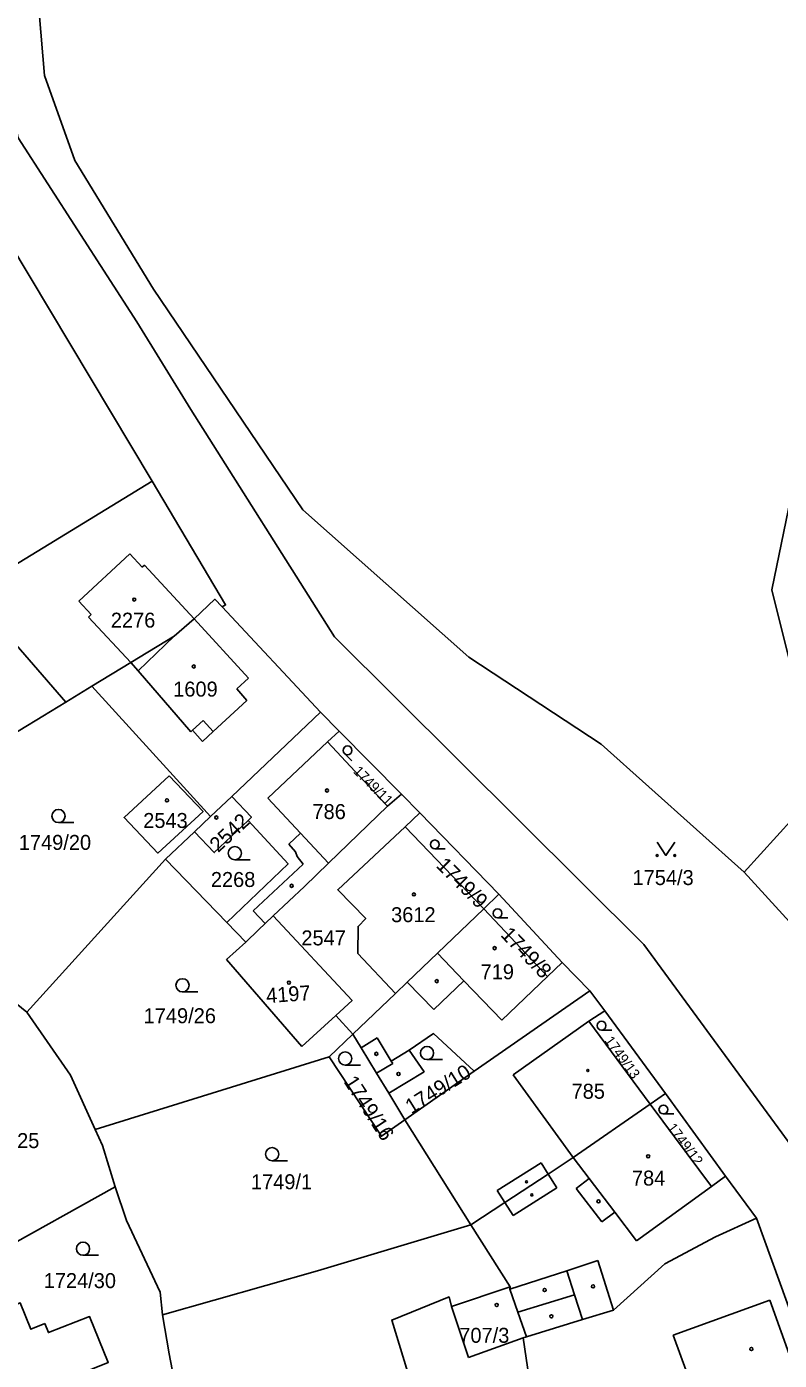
# Model space of a CAD drawing. Extents: x -679220 to -673243, y -1075091 to -1066557.
# Drawn here: x -676635.3 to -676549.8, y -1072087.4 to -1071935.7 of the extents above; entities that cross this region are included whole.
import ezdxf

# ---------------------------------------------------------------- set-up
doc = ezdxf.new("R2010")
doc.units = 0
for name, color, linetype in [('Hranice parcel', 7, 'Continuous'), ('Parcelní čísla', 7, 'Continuous'), ('Vnitřní kresba', 7, 'Continuous'), ('Značky budov', 7, 'Continuous'), ('Značky kultur', 7, 'Continuous')]:
    doc.layers.add(name, color=color, linetype=linetype)

msp = doc.modelspace()

# ---------------------------------------------------------------- linework, layer by layer
at = {"layer": 'Hranice parcel'}
for p, q in [((-676621.07, -1071987.4), (-676641.72, -1072000.02)), ((-676641.72, -1072000.02), (-676630.86, -1072012.51)), ((-676613.1, -1072001.69), (-676601.93, -1072013.64)), ((-676630.86, -1072012.51), (-676627.91, -1072010.71)), ((-676627.91, -1072010.71), (-676614.43, -1072025.51)), ((-676653.53, -1072026.32), (-676630.86, -1072012.51)), ((-676601.93, -1072013.64), (-676612.02, -1072023.23)), ((-676601.93, -1072013.64), (-676599.8, -1072015.8)), ((-676599.8, -1072015.8), (-676592.72, -1072022.97)), ((-676541.89, -1072018.69), (-676553.76, -1072031.84)), ((-676614.43, -1072025.51), (-676612.02, -1072023.23)), ((-676594.3, -1072024.34), (-676592.72, -1072022.97)), ((-676592.72, -1072022.97), (-676590.64, -1072025.11)), ((-676614.43, -1072025.51), (-676616.25, -1072027.25)), ((-676590.64, -1072025.11), (-676592.32, -1072026.68)), ((-676590.64, -1072025.11), (-676581.66, -1072034.34)), ((-676619.53, -1072030.36), (-676616.25, -1072027.25)), ((-676592.32, -1072026.68), (-676583.38, -1072036)), ((-676635.3, -1072047.75), (-676619.53, -1072030.36)), ((-676619.53, -1072030.36), (-676612.59, -1072037.56)), ((-676581.66, -1072034.34), (-676583.38, -1072036)), ((-676581.66, -1072034.34), (-676574.45, -1072042.12)), ((-676612.59, -1072037.56), (-676610.42, -1072039.82)), ((-676612.6, -1072041.77), (-676610.42, -1072039.82)), ((-676604.04, -1072051.67), (-676612.6, -1072041.77)), ((-676574.45, -1072042.12), (-676571.33, -1072045.34)), ((-676593.41, -1072045.63), (-676598.25, -1072050.28)), ((-676584.45, -1072054.47), (-676571.33, -1072045.34)), ((-676571.33, -1072045.34), (-676569.62, -1072047.62)), ((-676569.62, -1072047.62), (-676562.71, -1072057.02)), ((-676600.19, -1072048.13), (-676604.04, -1072051.67)), ((-676598.25, -1072050.28), (-676600.19, -1072048.13)), ((-676598.25, -1072050.28), (-676600.93, -1072052.86)), ((-676600.93, -1072052.86), (-676627.53, -1072061.09)), ((-676584.45, -1072054.47), (-676592.33, -1072060)), ((-676594.16, -1072056.99), (-676592.33, -1072060)), ((-676562.71, -1072057.02), (-676564.44, -1072058.21)), ((-676562.71, -1072057.02), (-676555.88, -1072066.4)), ((-676592.33, -1072060), (-676584.82, -1072071.93)), ((-676555.88, -1072066.4), (-676552.37, -1072071.2)), ((-676652.26, -1072082.65), (-676625.25, -1072067.62)), ((-676552.37, -1072071.2), (-676542.21, -1072099.31)), ((-676584.82, -1072071.93), (-676580.38, -1072079))]:
    msp.add_line(p, q, dxfattribs=at)
for points in [[(-676651.25, -1071520.53), (-676649.67, -1071525.28), (-676636.33, -1071567.59), (-676632.67, -1071580.29), (-676618.91, -1071616.92), (-676601.45, -1071672.26), (-676590.27, -1071707.98), (-676587.53, -1071724.18), (-676588.53, -1071766.09), (-676588.57, -1071776.49), (-676583.64, -1071788.99), (-676568.69, -1071809.98), (-676555.21, -1071828.53), (-676552.27, -1071835.54), (-676544.88, -1071865.16), (-676535.44, -1071910.25), (-676533.59, -1071921.04), (-676532.8, -1071927.61), (-676534.01, -1071935.8), (-676540.25, -1071959.64), (-676548.46, -1071989.23), (-676550.64, -1071999.75), (-676548.02, -1072010.25), (-676541.89, -1072018.69)], [(-676536.59, -1072122.5), (-676533.92, -1072098.22), (-676545.12, -1072067.43), (-676565.16, -1072040.09), (-676600.33, -1072005.09), (-676616.66, -1071979.22), (-676622.81, -1071969.28), (-676636.28, -1071948.34), (-676643.38, -1071915.55), (-676643.27, -1071912.66), (-676641.57, -1071878.93), (-676640.51, -1071869.39), (-676644.08, -1071858.21), (-676648.12, -1071848.64), (-676652.14, -1071843.11), (-676662.12, -1071830.1), (-676667.77, -1071822.29), (-676671.63, -1071816.16), (-676675.84, -1071808.46), (-676684.53, -1071784.41), (-676687.42, -1071776.51), (-676692.78, -1071762.77), (-676693.21, -1071759.8)], [(-676693.21, -1071759.8), (-676682.45, -1071780.64), (-676664.29, -1071814.93), (-676647.47, -1071846.25), (-676640.24, -1071862.09), (-676636.02, -1071877.65), (-676635.05, -1071901.27), (-676635.17, -1071919.29), (-676633.29, -1071941.26), (-676629.86, -1071950.91), (-676620.91, -1071965.54), (-676603.92, -1071990.64), (-676585.08, -1072007.38), (-676570.01, -1072017.31), (-676553.76, -1072031.84)], [(-676645.42, -1071936.13), (-676642.71, -1071947.04), (-676640.27, -1071954.61), (-676639.72, -1071956.26), (-676621.07, -1071987.4)], [(-676621.07, -1071987.4), (-676612.71, -1072001.45), (-676613.1, -1072001.69)], [(-676613.1, -1072001.69), (-676613.92, -1072000.81), (-676616.28, -1072003.03), (-676618.57, -1072005.02), (-676623.47, -1072008.01), (-676627.91, -1072010.71)], [(-676594.3, -1072024.34), (-676601.12, -1072017.04), (-676599.8, -1072015.8)], [(-676619.12, -1072020.89), (-676624.25, -1072025.62), (-676620.4, -1072029.67), (-676615.28, -1072024.94), (-676619.12, -1072020.89)], [(-676612.02, -1072023.23), (-676609.77, -1072025.59), (-676610.16, -1072025.96)], [(-676607.29, -1072036.83), (-676603.74, -1072033.46), (-676601, -1072030.84), (-676594.3, -1072024.34)], [(-676616.25, -1072027.25), (-676614.01, -1072029.61), (-676610.16, -1072025.96)], [(-676610.16, -1072025.96), (-676605.61, -1072030.88), (-676612.59, -1072037.56)], [(-676593.41, -1072045.63), (-676597.68, -1072041.1), (-676597.66, -1072038.02), (-676596.78, -1072037.12), (-676599.97, -1072033.85), (-676592.32, -1072026.68)], [(-676553.76, -1072031.84), (-676533.17, -1072054.44), (-676527.24, -1072064.82), (-676522.81, -1072075.75), (-676520.39, -1072086.47), (-676519.96, -1072097.33), (-676521.47, -1072117.29)], [(-676610.42, -1072039.82), (-676608.96, -1072038.42), (-676608.2, -1072037.7), (-676607.29, -1072036.83)], [(-676607.29, -1072036.83), (-676598.34, -1072046.42), (-676600.19, -1072048.13)], [(-676583.38, -1072036), (-676588.63, -1072041.05), (-676592.06, -1072044.34), (-676593.41, -1072045.63)], [(-676574.45, -1072042.12), (-676576.12, -1072043.71), (-676583.38, -1072036)], [(-676635.3, -1072047.75), (-676636.51, -1072046.77), (-676639.08, -1072044.43)], [(-676564.44, -1072058.21), (-676571.43, -1072048.77), (-676569.62, -1072047.62)], [(-676627.53, -1072061.09), (-676630.33, -1072054.92), (-676635.3, -1072047.75)], [(-676598.25, -1072050.28), (-676597.32, -1072051.81), (-676595.55, -1072054.71), (-676594.16, -1072056.99)], [(-676594.16, -1072056.99), (-676590.16, -1072054.55), (-676591.83, -1072052.1), (-676589.07, -1072050.2), (-676584.45, -1072054.47)], [(-676592.33, -1072060), (-676595, -1072061.87), (-676600.93, -1072052.86)], [(-676564.44, -1072058.21), (-676573.21, -1072064.31), (-676576.05, -1072066.17), (-676580.97, -1072069.4), (-676584.82, -1072071.93)], [(-676555.88, -1072066.4), (-676557.49, -1072067.59), (-676564.44, -1072058.21)], [(-676625.25, -1072067.62), (-676626.69, -1072062.94), (-676627.53, -1072061.09)], [(-676619.88, -1072082.19), (-676620.15, -1072079.6), (-676623.98, -1072071.44), (-676625.25, -1072067.62)], [(-676552.37, -1072071.2), (-676557.02, -1072073.3), (-676562.79, -1072076.4), (-676568.62, -1072081.66), (-676572.15, -1072082.73), (-676573.06, -1072079.9), (-676579.5, -1072081.87)], [(-676619.88, -1072082.19), (-676602.27, -1072077.16), (-676584.82, -1072071.93)], [(-676594.51, -1072100.12), (-676595.19, -1072097.87), (-676596.79, -1072093.24), (-676591.16, -1072091.48), (-676593.83, -1072082.77), (-676587.32, -1072080.15), (-676587.05, -1072081.24), (-676580.38, -1072079)], [(-676580.38, -1072079), (-676580.41, -1072079.26), (-676579.5, -1072081.87)], [(-676633.27, -1072083.18), (-676634.85, -1072083.83), (-676636.08, -1072080.81), (-676645.34, -1072084.58), (-676641.57, -1072093.86), (-676626.06, -1072087.6), (-676628.17, -1072082.38), (-676632.86, -1072084.2), (-676633.27, -1072083.18)], [(-676617.93, -1072092.96), (-676619.14, -1072086.6), (-676619.88, -1072082.19)], [(-676579.5, -1072081.87), (-676578.52, -1072084.67), (-676578.9, -1072084.79), (-676577.03, -1072097.37), (-676577.24, -1072097.44), (-676576.6, -1072102.13), (-676574.01, -1072101.78)]]:
    msp.add_lwpolyline(points, dxfattribs=at)
at = {"layer": 'Vnitřní kresba'}
for p, q in [((-676629.4, -1072001.02), (-676623.61, -1071995.66)), ((-676623.61, -1071995.66), (-676622.21, -1071997.18)), ((-676622.21, -1071997.18), (-676621.93, -1071996.93)), ((-676621.93, -1071996.93), (-676616.28, -1072003.03)), ((-676627.98, -1072002.56), (-676629.4, -1072001.02)), ((-676628.3, -1072002.85), (-676627.98, -1072002.56)), ((-676623.47, -1072008.01), (-676628.3, -1072002.85)), ((-676610.11, -1072009.79), (-676616.28, -1072003.03)), ((-676622.65, -1072008.95), (-676618.57, -1072005.02)), ((-676623.47, -1072008.01), (-676622.65, -1072008.95)), ((-676622.65, -1072008.95), (-676616.67, -1072015.87)), ((-676611.44, -1072011.01), (-676610.11, -1072009.79)), ((-676610.29, -1072012.33), (-676611.44, -1072011.01)), ((-676614.11, -1072015.84), (-676610.29, -1072012.33)), ((-676616.67, -1072015.87), (-676616.46, -1072015.69)), ((-676615.26, -1072014.59), (-676616.46, -1072015.69)), ((-676616.46, -1072015.69), (-676615.35, -1072016.97)), ((-676614.11, -1072015.84), (-676615.26, -1072014.59)), ((-676615.35, -1072016.97), (-676614.11, -1072015.84)), ((-676601.12, -1072017.04), (-676607.93, -1072023.42)), ((-676607.93, -1072023.42), (-676604.19, -1072027.41)), ((-676604.19, -1072027.41), (-676605.54, -1072028.68)), ((-676604.19, -1072027.41), (-676601, -1072030.84)), ((-676605.54, -1072028.68), (-676604.75, -1072029.52)), ((-676603.91, -1072030.92), (-676609.58, -1072036.23)), ((-676604.75, -1072029.52), (-676604.59, -1072030.05)), ((-676604.59, -1072030.05), (-676603.91, -1072030.92)), ((-676609.58, -1072036.23), (-676608.2, -1072037.7)), ((-676585.62, -1072044.19), (-676588.63, -1072041.05)), ((-676592.06, -1072044.34), (-676589.05, -1072047.48)), ((-676589.05, -1072047.48), (-676585.62, -1072044.19)), ((-676585.62, -1072044.19), (-676581.33, -1072048.67)), ((-676581.33, -1072048.67), (-676576.12, -1072043.71)), ((-676580.02, -1072054.91), (-676571.43, -1072048.77)), ((-676595.48, -1072050.7), (-676597.32, -1072051.81)), ((-676593.88, -1072053.34), (-676595.48, -1072050.7)), ((-676593.88, -1072053.34), (-676591.83, -1072052.1)), ((-676595.55, -1072054.71), (-676593.72, -1072053.6)), ((-676593.72, -1072053.6), (-676593.88, -1072053.34)), ((-676573.21, -1072064.31), (-676580.02, -1072054.91)), ((-676571.4, -1072066.69), (-676573.21, -1072064.31)), ((-676581.83, -1072068.04), (-676576.84, -1072064.91)), ((-676576.84, -1072064.91), (-676576.05, -1072066.17)), ((-676576.05, -1072066.17), (-676575.06, -1072067.75)), ((-676571.4, -1072066.69), (-676572.87, -1072067.81)), ((-676568.49, -1072070.5), (-676571.4, -1072066.69)), ((-676580.97, -1072069.4), (-676581.83, -1072068.04)), ((-676575.06, -1072067.75), (-676580.04, -1072070.88)), ((-676572.87, -1072067.81), (-676569.96, -1072071.62)), ((-676557.49, -1072067.59), (-676566, -1072073.78)), ((-676580.04, -1072070.88), (-676580.97, -1072069.4)), ((-676569.96, -1072071.62), (-676568.49, -1072070.5)), ((-676566, -1072073.78), (-676568.49, -1072070.5)), ((-676573.94, -1072077.16), (-676570.4, -1072076.01)), ((-676570.4, -1072076.01), (-676568.62, -1072081.66)), ((-676580.41, -1072079.26), (-676573.94, -1072077.16)), ((-676573.06, -1072079.9), (-676573.94, -1072077.16)), ((-676550.85, -1072080.53), (-676561.84, -1072084.49)), ((-676546.84, -1072091.68), (-676550.85, -1072080.53)), ((-676587.05, -1072081.24), (-676585.1, -1072087.03)), ((-676578.52, -1072084.67), (-676572.15, -1072082.73)), ((-676585.1, -1072087.03), (-676578.9, -1072084.79)), ((-676561.84, -1072084.49), (-676560.26, -1072088.87))]:
    msp.add_line(p, q, dxfattribs=at)
at = {"layer": 'Značky budov'}
for centre, radius in [((-676623.1, -1072000.85), 0.175), ((-676616.33, -1072008.46), 0.175), ((-676601.18, -1072022.56), 0.175), ((-676619.38, -1072023.68), 0.175), ((-676613.76, -1072025.63), 0.175), ((-676605.21, -1072033.4), 0.175), ((-676591.31, -1072034.38), 0.175), ((-676582.13, -1072040.49), 0.175), ((-676605.52, -1072044.41), 0.175), ((-676588.71, -1072044.24), 0.175), ((-676595.58, -1072052.5), 0.175), ((-676593.06, -1072054.79), 0.175), ((-676571.54, -1072054.4), 0.117), ((-676564.68, -1072064.15), 0.175), ((-676578.5, -1072067.06), 0.117), ((-676577.9, -1072068.55), 0.117), ((-676570.33, -1072069.28), 0.175), ((-676576.45, -1072079.36), 0.175), ((-676570.95, -1072078.95), 0.175), ((-676581.9, -1072081.06), 0.175), ((-676575.68, -1072082.35), 0.175), ((-676552.95, -1072086.07), 0.175)]:
    msp.add_circle(centre, radius, dxfattribs=at)
at = {"layer": 'Značky kultur'}
for p, q in [((-676599.21, -1072018.35), (-676598.38, -1072019.18)), ((-676631.7, -1072026.21), (-676629.95, -1072026.21)), ((-676588.93, -1072029.19), (-676587.75, -1072029.19)), ((-676611.66, -1072030.44), (-676609.91, -1072030.44)), ((-676581.8, -1072037.03), (-676580.62, -1072037.03)), ((-676617.62, -1072045.46), (-676615.87, -1072045.46)), ((-676569.97, -1072049.8), (-676568.8, -1072049.8)), ((-676589.82, -1072053.16), (-676588.07, -1072053.16)), ((-676599.13, -1072053.79), (-676597.38, -1072053.79)), ((-676562.95, -1072059.34), (-676561.77, -1072059.34)), ((-676607.43, -1072064.66), (-676605.68, -1072064.66)), ((-676628.92, -1072075.41), (-676627.17, -1072075.41))]:
    msp.add_line(p, q, dxfattribs=at)
msp.add_lwpolyline([(-676563.66, -1072028.45), (-676562.66, -1072029.95), (-676561.66, -1072028.45)], dxfattribs=at)
for centre, radius in [((-676598.85, -1072018), 0.502), ((-676631.7, -1072025.46), 0.75), ((-676611.66, -1072029.69), 0.75), ((-676588.93, -1072028.69), 0.502), ((-676563.66, -1072029.95), 0.1), ((-676561.66, -1072029.95), 0.1), ((-676581.8, -1072036.53), 0.502), ((-676617.62, -1072044.71), 0.75), ((-676569.98, -1072049.3), 0.502), ((-676589.82, -1072052.41), 0.75), ((-676599.13, -1072053.04), 0.75), ((-676562.95, -1072058.84), 0.502), ((-676607.43, -1072063.91), 0.75), ((-676628.92, -1072074.66), 0.75)]:
    msp.add_circle(centre, radius, dxfattribs=at)

# ---------------------------------------------------------------- texts
at = {"layer": 'Parcelní čísla'}
for s, p in [('2276', (-676625.76, -1072004.04)), ('1609', (-676618.67, -1072011.88)), ('786', (-676602.84, -1072025.81)), ('2543', (-676622.08, -1072026.82)), ('1749/20', (-676636.22, -1072029.31)), ('2268', (-676614.39, -1072033.53)), ('1754/3', (-676566.46, -1072033.31)), ('3612', (-676593.9, -1072037.53)), ('2547', (-676604.1, -1072040.17)), ('719', (-676583.73, -1072044.02)), ('1749/26', (-676622.03, -1072049.02)), ('785', (-676573.39, -1072057.61)), ('1724/25', (-676642.1, -1072063.22)), ('784', (-676566.53, -1072067.48)), ('1749/1', (-676609.83, -1072067.9)), ('1724/30', (-676633.39, -1072079.14)), ('707/3', (-676586.15, -1072085.36))]:
    msp.add_text(s, height=1.7, dxfattribs=at).set_placement(p)
for s, height, rotation, p in [('1749/11', 1.14, 315, (-676598.27, -1072020.46)), ('2542', 1.7, 43, (-676613.56, -1072029.69)), ('1749/9', 1.7, 315, (-676588.87, -1072031.19)), ('1749/8', 1.7, 314, (-676581.55, -1072039.06)), ('4197', 1.7, 4, (-676608.05, -1072046.74)), ('1749/13', 1.14, 306, (-676569.69, -1072051)), ('1749/16', 1.7, 303, (-676599.35, -1072055.67)), ('1749/10', 1.7, 32, (-676591.61, -1072059.39)), ('1749/12', 1.14, 307, (-676562.58, -1072060.92))]:
    msp.add_text(s, height=height, rotation=rotation, dxfattribs=at).set_placement(p)

doc.saveas('drawing.dxf')
